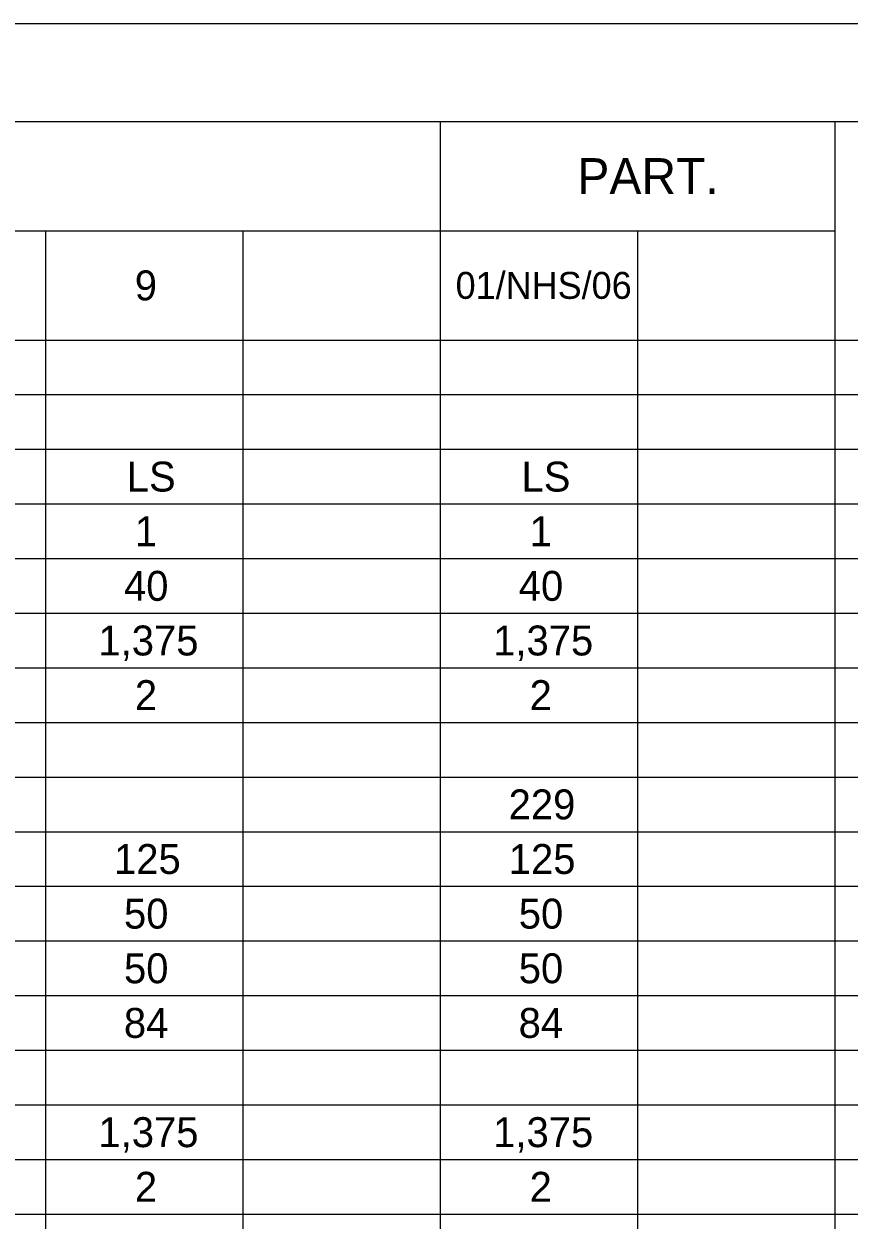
# Model space of a CAD drawing. Extents: x 0 to 34, y 0 to 22.
# Drawn here: x 5.44 to 9.67, y 15.87 to 22 of the extents above; entities that cross this region are included whole.
import ezdxf

# ---------------------------------------------------------------- set-up
doc = ezdxf.new("R2010")
doc.units = 0
for name, color, linetype in [('SH_Border', 7, 'Continuous'), ('SH_Cut_Line', 7, 'Continuous'), ('SH_Text', 7, 'Continuous')]:
    doc.layers.add(name, color=color, linetype=linetype)

msp = doc.modelspace()

# ---------------------------------------------------------------- linework, layer by layer
at = {"layer": 'SH_Border'}
msp.add_lwpolyline([(1.5, 21.5), (33.5, 21.5), (33.5, 0.5), (1.5, 0.5)], close=True, dxfattribs=at)
at = {"layer": 'SH_Cut_Line'}
msp.add_lwpolyline([(0, 0), (34, 0), (34, 22), (0, 22)], close=True, dxfattribs=at)
at = {"layer": 'SH_Text'}
for p, q in [((1.5, 21.5), (6.5595, 21.5)), ((6.5595, 21.5), (7.5715, 21.5)), ((7.5715, 21.5), (13.3316, 21.5)), ((7.5715, 21.5), (7.5715, 21.22)), ((9.5953, 21.5), (9.5953, 21.22)), ((7.5715, 21.22), (7.5715, 20.94)), ((9.5953, 21.22), (9.5953, 20.94)), ((1.5, 20.94), (6.5595, 20.94)), ((5.5476, 20.94), (5.5476, 20.66)), ((6.5595, 20.94), (7.5715, 20.94)), ((6.5595, 20.94), (6.5595, 20.66)), ((7.5715, 20.94), (9.5953, 20.94)), ((7.5715, 20.94), (7.5715, 20.66)), ((8.5834, 20.94), (8.5834, 20.66)), ((9.5953, 20.94), (9.5953, 20.66)), ((5.5476, 20.66), (5.5476, 20.38)), ((6.5595, 20.66), (6.5595, 20.38)), ((7.5715, 20.66), (7.5715, 20.38)), ((8.5834, 20.66), (8.5834, 20.38)), ((9.5953, 20.66), (9.5953, 20.38)), ((1.5, 20.38), (6.5595, 20.38)), ((5.5476, 20.38), (5.5476, 20.1)), ((6.5595, 20.38), (7.5715, 20.38)), ((6.5595, 20.38), (6.5595, 20.1)), ((7.5715, 20.38), (13.3316, 20.38)), ((7.5715, 20.38), (7.5715, 20.1)), ((8.5834, 20.38), (8.5834, 20.1)), ((9.5953, 20.38), (9.5953, 20.1)), ((1.5, 20.1), (6.5595, 20.1)), ((5.5476, 20.1), (5.5476, 18.7)), ((6.5595, 20.1), (7.5715, 20.1)), ((6.5595, 20.1), (6.5595, 18.7)), ((7.5715, 20.1), (13.3316, 20.1)), ((7.5715, 20.1), (7.5715, 18.7)), ((8.5834, 20.1), (8.5834, 18.7)), ((9.5953, 20.1), (9.5953, 18.7)), ((1.5, 19.82), (6.5595, 19.82)), ((6.5595, 19.82), (7.5715, 19.82)), ((7.5715, 19.82), (13.3316, 19.82)), ((1.5, 19.54), (6.5595, 19.54)), ((6.5595, 19.54), (7.5715, 19.54)), ((7.5715, 19.54), (13.3316, 19.54)), ((1.5, 19.26), (6.5595, 19.26)), ((6.5595, 19.26), (7.5715, 19.26)), ((7.5715, 19.26), (13.3316, 19.26)), ((1.5, 18.98), (6.5595, 18.98)), ((6.5595, 18.98), (7.5715, 18.98)), ((7.5715, 18.98), (13.3316, 18.98)), ((1.5, 18.7), (6.5595, 18.7)), ((5.5476, 18.7), (5.5476, 18.14)), ((6.5595, 18.7), (7.5715, 18.7)), ((6.5595, 18.7), (6.5595, 18.14)), ((7.5715, 18.7), (13.3316, 18.7)), ((7.5715, 18.7), (7.5715, 18.14)), ((8.5834, 18.7), (8.5834, 18.14)), ((9.5953, 18.7), (9.5953, 18.14)), ((1.5, 18.42), (6.5595, 18.42)), ((6.5595, 18.42), (7.5715, 18.42)), ((7.5715, 18.42), (13.3316, 18.42)), ((1.5, 18.14), (6.5595, 18.14)), ((5.5476, 18.14), (5.5476, 17.86)), ((6.5595, 18.14), (7.5715, 18.14)), ((6.5595, 18.14), (6.5595, 17.86)), ((7.5715, 18.14), (13.3316, 18.14)), ((7.5715, 18.14), (7.5715, 17.86)), ((8.5834, 18.14), (8.5834, 17.86)), ((9.5953, 18.14), (9.5953, 17.86)), ((1.5, 17.86), (6.5595, 17.86)), ((5.5476, 17.86), (5.5476, 17.58)), ((6.5595, 17.86), (7.5715, 17.86)), ((6.5595, 17.86), (6.5595, 17.58)), ((7.5715, 17.86), (13.3316, 17.86)), ((7.5715, 17.86), (7.5715, 17.58)), ((8.5834, 17.86), (8.5834, 17.58)), ((9.5953, 17.86), (9.5953, 17.58)), ((1.5, 17.58), (6.5595, 17.58)), ((5.5476, 17.58), (5.5476, 17.3)), ((6.5595, 17.58), (7.5715, 17.58)), ((6.5595, 17.58), (6.5595, 17.3)), ((7.5715, 17.58), (13.3316, 17.58)), ((7.5715, 17.58), (7.5715, 17.3)), ((8.5834, 17.58), (8.5834, 17.3)), ((9.5953, 17.58), (9.5953, 17.3)), ((1.5, 17.3), (6.5595, 17.3)), ((5.5476, 17.3), (5.5476, 17.02)), ((6.5595, 17.3), (7.5715, 17.3)), ((6.5595, 17.3), (6.5595, 17.02)), ((7.5715, 17.3), (13.3316, 17.3)), ((7.5715, 17.3), (7.5715, 17.02)), ((8.5834, 17.3), (8.5834, 17.02)), ((9.5953, 17.3), (9.5953, 17.02)), ((1.5, 17.02), (6.5595, 17.02)), ((5.5476, 17.02), (5.5476, 16.74)), ((6.5595, 17.02), (7.5715, 17.02)), ((6.5595, 17.02), (6.5595, 16.74)), ((7.5715, 17.02), (13.3316, 17.02)), ((7.5715, 17.02), (7.5715, 16.74)), ((8.5834, 17.02), (8.5834, 16.74)), ((9.5953, 17.02), (9.5953, 16.74)), ((1.5, 16.74), (6.5595, 16.74)), ((5.5476, 16.74), (5.5476, 16.18)), ((6.5595, 16.74), (7.5715, 16.74)), ((6.5595, 16.74), (6.5595, 16.18)), ((7.5715, 16.74), (13.3316, 16.74)), ((7.5715, 16.74), (7.5715, 16.18)), ((8.5834, 16.74), (8.5834, 16.18)), ((9.5953, 16.74), (9.5953, 16.18)), ((1.5, 16.46), (6.5595, 16.46)), ((6.5595, 16.46), (7.5715, 16.46)), ((7.5715, 16.46), (13.3316, 16.46)), ((1.5, 16.18), (6.5595, 16.18)), ((5.5476, 16.18), (5.5476, 15.9)), ((6.5595, 16.18), (7.5715, 16.18)), ((6.5595, 16.18), (6.5595, 15.9)), ((7.5715, 16.18), (13.3316, 16.18)), ((7.5715, 16.18), (7.5715, 15.9)), ((8.5834, 16.18), (8.5834, 15.9)), ((9.5953, 16.18), (9.5953, 15.9)), ((1.5, 15.9), (6.5595, 15.9)), ((5.5476, 15.9), (5.5476, 15.62)), ((6.5595, 15.9), (7.5715, 15.9)), ((6.5595, 15.9), (6.5595, 15.62)), ((7.5715, 15.9), (13.3316, 15.9)), ((7.5715, 15.9), (7.5715, 15.62)), ((8.5834, 15.9), (8.5834, 15.62)), ((9.5953, 15.9), (9.5953, 15.62))]:
    msp.add_line(p, q, dxfattribs=at)

# ---------------------------------------------------------------- texts
for s, height, p in [('PART.', 0.184, (8.2747, 21.128)), ('9', 0.1533, (6.0054, 20.5833)), ('01/NHS/06', 0.138, (7.6503, 20.591)), ('LS', 0.15333, (5.9644, 19.6033)), ('LS', 0.15333, (7.9882, 19.6033)), ('1', 0.1533, (6.0057, 19.3233)), ('1', 0.1533, (8.0296, 19.3233)), ('40', 0.15333, (5.9501, 19.0433)), ('40', 0.15333, (7.9739, 19.0433)), ('1,375', 0.15333, (5.819, 18.7633)), ('1,375', 0.15333, (7.8428, 18.7633)), ('2', 0.1533, (6.0059, 18.4833)), ('2', 0.1533, (8.0297, 18.4833)), ('229', 0.15333, (7.922, 17.9233)), ('125', 0.15333, (5.899, 17.6433)), ('125', 0.15333, (7.9228, 17.6433)), ('50', 0.15333, (5.9501, 17.3633)), ('50', 0.15333, (7.9739, 17.3633)), ('50', 0.15333, (5.9501, 17.0833)), ('50', 0.15333, (7.9739, 17.0833)), ('84', 0.15333, (5.9495, 16.8033)), ('84', 0.15333, (7.9733, 16.8033)), ('1,375', 0.15333, (5.819, 16.2433)), ('1,375', 0.15333, (7.8428, 16.2433)), ('2', 0.1533, (6.0059, 15.9633)), ('2', 0.1533, (8.0297, 15.9633))]:
    msp.add_text(s, height=height, dxfattribs=at).set_placement(p)

doc.saveas('drawing.dxf')
